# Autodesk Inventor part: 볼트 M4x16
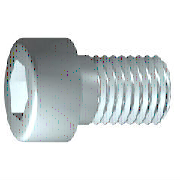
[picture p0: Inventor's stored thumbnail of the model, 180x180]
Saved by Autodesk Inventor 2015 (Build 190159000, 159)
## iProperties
IsCustomPart: 1
Created: 2012-02
Part Number: 볼트 M4x16
Material: 강철, 연강
Description: 6각머리 태핑 나사
Document SubType Name: Modeling
Standard: KS B 1003
Designer: mduedu
Standards Organization: KS
Language: ko-KR
Size Designation: M 4 x 16
Categories: <MemberInstance><Categories><Category DisplayName="조임쇠" InternalName="e4da775c-781d-43d5-af7c-5136215cf5a6" Mnemonic="FSTN"><Category DisplayName="볼트" InternalN
Density: 1 g/cm^3
Appearance: 강철
Author: mduedu
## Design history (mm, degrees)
sketch "스케치1"
  geometry: L1 (-1, 0)-(16, 0); L2 (16, 0)-(16, 2); L3 (16, 2)-(1.75, 2); L4 (1.75, 2)-(1.32, 2); L5 (1.32, 2)-(0, 2); L6 (0, 2)-(0, 3.5); L7 (0, 3.5)-(-4, 3.5); L8 (-4, 3.5)-(-4, 1.732); L9 (-4, 1.732)-(-2, 1.732); L10 (-2, 1.732)-(-1, 0); L11 (-8, 0)-(20, 0) reference; L12 (0, -0.7)-(0, 4.2) reference; L13 (1.75, 2)-(0, 2)
  constraints: 22 end point, 6 parallel, 2 collinear, 2 perpendicular, 1 horizontal, 1 point on line
  dimensions: "d1" = 14.25 distance from line of L3.end L2 (= GEL); "d2" = 0.42952 distance of L4.end L3.end (computed from GAL); "d3" = 4 distance between parallel lines of L8 L6 (= KOH); "d4" = 2 distance of L8.end L9.end (= INTI); "d5" = 60 deg angle of L10 L1; "d6" = 4 diameter of L3 L1 (= GD); "d7" = 4 diameter of L5 L1 (= BDM); "d8" = 3.4641 diameter of L9 L1 (= 1.1547 x SW); "d9" = 7 diameter of L7 L1 (= KOD); "d26" = 16 distance between parallel lines of L12 L2 (= NLG)
revolve "본체" sketch "스케치1" stored, may be unused: angle "d10" = 90 deg
sketch "스케치2"
  geometry: L1 (0, -4.9)-(0, 4.9) reference; L2 (-4.9, 0)-(4.9, 0) reference; L3 (1.732, 0)-(0.866, -1.5); L4 (0.866, -1.5)-(-0.866, -1.5); L5 (-0.866, -1.5)-(-1.732, 0); L6 (-1.732, 0)-(-0.866, 1.5); L7 (-0.866, 1.5)-(0.866, 1.5); L8 (0.866, 1.5)-(1.732, 0); 2 further points
  constraints: 12 end point, 1 coincident, 1 horizontal alignment, 1 point on line, 12 other
extrude "슬롯" join sketch "스케치2" stored distance "d11" = 10; taper "d12" = 0 deg
workplane "Work Plane1"
fillet "Fillet2" dims "d30" = 0.1 (= R)
body "Solid1"
fillet "모깎기1" dims "d17" = 0.4 (= RR)
feature "스레드" dims "d13" = 14.25 (= GEL), "d14" = 0
chamfer "모따기1" distance "d15" = 0.42941 (= -0.5 x SPD + 0.5 x GD); stored, may be unused: second distance "d16" = 0.42941 (= GUL), angle "d27" = 45 deg
other parameters: "GD" = 4 (= NND) [user parameter; used in 2 equation terms], "NLG" = 16 [user parameter; used in 1 equation term], "GEL" = 14.25 [user parameter; used in 2 equation terms], "KOD" = 7 [user parameter; used in 1 equation term], "KOH" = 4 [user parameter; used in 1 equation term], "INTI" = 2 [user parameter; used in 1 equation term], "GAL" = 0.42941 (= 0.61345 x PTC) [user parameter; used in 1 equation term], "GUL" = 0.42941 (= 0.61345 x PTC) [user parameter; used in 1 equation term], "BDM" = 4 (= NND) [user parameter; used in 1 equation term], "SW" = 3 [user parameter; used in 2 equation terms], "RR" = 0.4 [user parameter; used in 1 equation term], "SPD" = 3.14117 (= NND - 1.2269 x PTC) [user parameter; used in 1 equation term], "d19" = 0, "d28" = 0, "d29" = 0, "R" = 0.1 [user parameter; used in 1 equation term], "PHH" = 0.2 [user parameter], "GD1" = 3.14117 (= THREADDIA - 1.2269 x PTC) [user parameter], "THREADDIA" = 4 [user parameter; used in 1 equation term], "FAWI" = 45 deg [user parameter], "TPU" = 14.28571 (computed from PTC) [user parameter], "PTC" = 0.7 [user parameter; used in 5 equation terms], "NND" = 4 [user parameter; used in 3 equation terms], "TOA" = 30 deg [user parameter], "E0" = 3.465 (= 1.155 x SW) [user parameter]
